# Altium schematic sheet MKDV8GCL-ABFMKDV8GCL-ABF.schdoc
size 127 x 101 mm
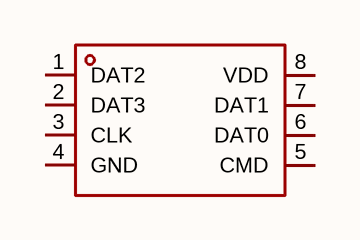
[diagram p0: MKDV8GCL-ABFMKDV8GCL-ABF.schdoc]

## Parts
U?  mkdv8gcl-abf  [LGA-8_L8.0-W6.0-P1.27-TL_ZDSD02GLGEAG]  (value not drawn)

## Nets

Not connected (* = marked no-connect by the designer): U? 1(DAT2) 2(DAT3) 3(CLK) 4(GND) 5(CMD) 6(DAT0) 7(DAT1) 8(VDD)

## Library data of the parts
U? = mkdv8gcl-abf: 存储容量:8Gbit;时钟频率(fc):50MHz;工作电压:2.7V~3.6V;; Manufacturer: MK(米客方德); AddInBom: yes; ModelId: d6f62e75701c4a978976e357bad77972; ModelTransform: 314.96,236.22,0,0,0,0,0,0,0; Memory Size: 8Gbit; Interface: SD接口; Clock Frequency: 50MHz; Data Retention - TDR (Year): 10年; Standby Supply Current: 80uA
